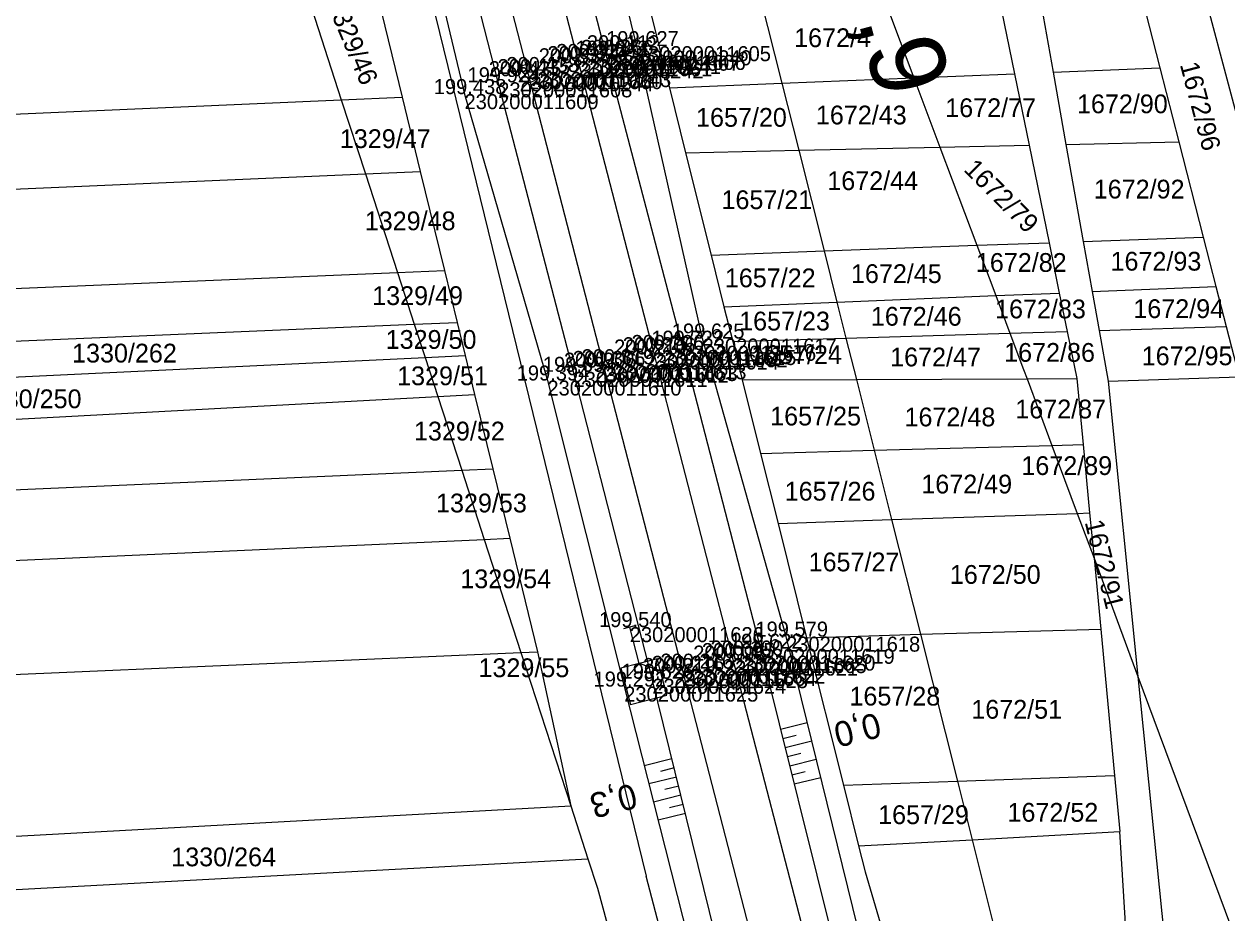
# Model space of a CAD drawing. Extents: x -563148 to -561712, y -1182311 to -1179502.
# Drawn here: x -562432.1 to -562336.1, y -1182118.9 to -1182047.9 of the extents above; entities that cross this region are included whole.
import ezdxf

# ---------------------------------------------------------------- set-up
doc = ezdxf.new("R2010")
doc.units = 0
for name, color, linetype in [('Vrstva 1', 7, 'Continuous'), ('Vrstva 4', 7, 'Continuous'), ('Vrstva 48', 7, 'Continuous'), ('Vrstva 49', 7, 'Continuous'), ('Vrstva 53', 7, 'Continuous'), ('Vrstva 55', 7, 'Continuous'), ('Vrstva 57', 7, 'Continuous'), ('Vrstva 60', 7, 'Continuous'), ('Vrstva 61', 7, 'Continuous'), ('Vrstva 7', 7, 'Continuous')]:
    doc.layers.add(name, color=color, linetype=linetype)

msp = doc.modelspace()

# ---------------------------------------------------------------- linework, layer by layer
at = {"layer": 'Vrstva 1'}
for points in [[(-562431.456, -1181882.158), (-562425.093, -1181906.771), (-562419.091, -1181930.016), (-562412.913, -1181953.965), (-562405.427, -1181982.918), (-562399.924, -1182004.215), (-562394.072, -1182026.888), (-562387.874, -1182050.84), (-562381.86, -1182074.092), (-562375.538, -1182098.521), (-562369.352, -1182122.433), (-562362.844, -1182147.635), (-562356.836, -1182170.919), (-562350.524, -1182195.336)], [(-562435.353, -1181883.455), (-562429.043, -1181907.884), (-562423.025, -1181931.202), (-562416.86, -1181955.033), (-562409.363, -1181984.042), (-562403.855, -1182005.364), (-562398.009, -1182028.011), (-562391.856, -1182051.875), (-562385.852, -1182075.188), (-562379.546, -1182099.541), (-562373.358, -1182123.485), (-562366.843, -1182148.681), (-562360.825, -1182171.976), (-562354.524, -1182196.409)]]:
    msp.add_lwpolyline(points, dxfattribs=at)
at = {"layer": 'Vrstva 4'}
for points in [[(-562356.597, -1182197.058), (-562363.671, -1182172.63), (-562369.111, -1182150.394), (-562376.003, -1182124.384), (-562381.959, -1182100.171), (-562388.242, -1182075.655), (-562394.258, -1182052.529), (-562401.091, -1182025.773), (-562406.12, -1182006.052), (-562411.703, -1181984.696), (-562419.188, -1181956.156), (-562425.491, -1181931.882), (-562431.354, -1181908.293), (-562438.222, -1181883.645), (-562444.124, -1181860.119), (-562450.397, -1181835.425), (-562455.984, -1181813.76), (-562461.844, -1181791.501), (-562470.013, -1181759.746), (-562475.447, -1181735.97), (-562481.267, -1181709.546), (-562485.292, -1181688.623), (-562489.631, -1181662.779), (-562492.854, -1181639.283)], [(-562429.083, -1181881.427), (-562423.039, -1181906.026), (-562416.991, -1181929.289), (-562410.946, -1181952.751), (-562403.313, -1181982.397), (-562397.583, -1182003.414), (-562392.555, -1182023.727), (-562385.634, -1182050.403), (-562379.578, -1182073.569), (-562373.303, -1182097.775), (-562367.317, -1182121.855), (-562360.795, -1182147.202), (-562354.718, -1182170.426), (-562348.388, -1182194.775)]]:
    msp.add_lwpolyline(points, dxfattribs=at)
at = {"layer": 'Vrstva 48'}
for p, q in [((-562371.705, -1182104.204), (-562369.577, -1182103.675)), ((-562371.524, -1182104.932), (-562370.461, -1182104.668)), ((-562371.343, -1182105.66), (-562369.219, -1182105.132)), ((-562380.385, -1182106.569), (-562382.596, -1182107.113)), ((-562371.162, -1182106.388), (-562370.101, -1182106.124)), ((-562370.981, -1182107.116), (-562368.86, -1182106.588)), ((-562380.206, -1182107.297), (-562381.309, -1182107.569)), ((-562370.8, -1182107.844), (-562369.74, -1182107.58)), ((-562380.027, -1182108.026), (-562382.227, -1182108.567)), ((-562370.619, -1182108.571), (-562368.502, -1182108.045)), ((-562379.669, -1182109.482), (-562381.858, -1182110.021)), ((-562379.848, -1182108.754), (-562380.945, -1182109.024)), ((-562379.489, -1182110.211), (-562380.581, -1182110.479)), ((-562379.31, -1182110.939), (-562381.489, -1182111.475))]:
    msp.add_line(p, q, dxfattribs=at)
at = {"layer": 'Vrstva 49'}
for points in [[(-562356.597, -1182197.058), (-562363.671, -1182172.63), (-562369.111, -1182150.394), (-562376.003, -1182124.384), (-562381.959, -1182100.171), (-562388.242, -1182075.655), (-562394.258, -1182052.529), (-562401.091, -1182025.773), (-562406.12, -1182006.052), (-562411.703, -1181984.696), (-562419.188, -1181956.156), (-562425.491, -1181931.882), (-562431.354, -1181908.293), (-562438.222, -1181883.645), (-562444.124, -1181860.119), (-562450.397, -1181835.425), (-562455.984, -1181813.76), (-562461.844, -1181791.501), (-562470.013, -1181759.746), (-562475.447, -1181735.97), (-562481.267, -1181709.546), (-562485.292, -1181688.623), (-562489.631, -1181662.779), (-562492.854, -1181639.283)], [(-562348.388, -1182194.775), (-562346.233, -1182193.909), (-562352.64, -1182170.226), (-562359.021, -1182146.828), (-562365.116, -1182121.8), (-562371.268, -1182096.806), (-562377.938, -1182072.997), (-562383.189, -1182049.641), (-562389.659, -1182023.356), (-562394.989, -1182002.824), (-562400.393, -1181981.55), (-562407.655, -1181951.839), (-562413.753, -1181928.351), (-562419.93, -1181905.004), (-562426.042, -1181880.285)], [(-562429.083, -1181881.427), (-562423.039, -1181906.026), (-562416.991, -1181929.289), (-562410.946, -1181952.751), (-562403.313, -1181982.397), (-562397.583, -1182003.414), (-562392.555, -1182023.727), (-562385.634, -1182050.403), (-562379.578, -1182073.569), (-562373.303, -1182097.775), (-562367.317, -1182121.855), (-562360.795, -1182147.202), (-562354.718, -1182170.426), (-562348.388, -1182194.775)], [(-562439.741, -1181884.96), (-562433.646, -1181909.277), (-562427.61, -1181932.656), (-562421.237, -1181957.617), (-562414.263, -1181985.119), (-562408.778, -1182006.666), (-562403.486, -1182026.149), (-562396.951, -1182053.474), (-562390.332, -1182076.348), (-562384.199, -1182100.797), (-562378.1, -1182124.825), (-562372.04, -1182148.774), (-562365.699, -1182172.919), (-562358.847, -1182197.091), (-562356.597, -1182197.058)]]:
    msp.add_lwpolyline(points, dxfattribs=at)
at = {"layer": 'Vrstva 53'}
for p, q in [((-562383.3, -1182042.07), (-562380.58, -1182052.97)), ((-562399.59, -1182045.91), (-562382.44, -1182115.94)), ((-562380.58, -1182052.97), (-562379.29, -1182058.16)), ((-562379.29, -1182058.16), (-562377.25, -1182066.33)), ((-562377.25, -1182066.33), (-562376.23, -1182070.45)), ((-562376.23, -1182070.45), (-562375.53, -1182073.24)), ((-562375.53, -1182073.24), (-562374.77, -1182076.29)), ((-562374.77, -1182076.29), (-562373.3, -1182082.17)), ((-562373.3, -1182082.17), (-562371.91, -1182087.77)), ((-562371.91, -1182087.77), (-562369.63, -1182096.89)), ((-562369.63, -1182096.89), (-562366.69, -1182108.67)), ((-562366.69, -1182108.67), (-562365.48, -1182113.52)), ((-562356.42, -1182113.03), (-562344.61, -1182112.38)), ((-562341.98, -1182156.11), (-562344.61, -1182112.38)), ((-562365.48, -1182113.52), (-562356.42, -1182113.03)), ((-562356.42, -1182113.03), (-562344.71, -1182159.58)), ((-562365.48, -1182113.52), (-562364.96, -1182115.6)), ((-562364.45, -1182184.72), (-562382.44, -1182115.94)), ((-562364.96, -1182115.6), (-562344.91, -1182183.41))]:
    msp.add_line(p, q, dxfattribs=at)
at = {"layer": 'Vrstva 55'}
for p, q in [((-562374.32, -1182041.85), (-562371.61, -1182052.6)), ((-562355.18, -1182041.39), (-562353.04, -1182051.84)), ((-562351.78, -1182041.39), (-562349.95, -1182051.71)), ((-562410.36, -1182042.92), (-562406.79, -1182053.92)), ((-562404.05, -1182045.04), (-562401.94, -1182053.71)), ((-562343.19, -1182044.49), (-562341.43, -1182051.36)), ((-562338.04, -1182044.82), (-562329.82, -1182075.89)), ((-562363.26, -1182046.36), (-562361.07, -1182052.17)), ((-562361.07, -1182052.17), (-562353.04, -1182051.84)), ((-562353.04, -1182051.84), (-562351.87, -1182057.55)), ((-562349.95, -1182051.71), (-562341.43, -1182051.36)), ((-562349.95, -1182051.71), (-562348.92, -1182057.49)), ((-562341.43, -1182051.36), (-562339.9, -1182057.29)), ((-562380.58, -1182052.97), (-562371.61, -1182052.6)), ((-562371.61, -1182052.6), (-562361.07, -1182052.17)), ((-562371.61, -1182052.6), (-562370.26, -1182057.96)), ((-562361.07, -1182052.17), (-562358.99, -1182057.71)), ((-562406.79, -1182053.92), (-562401.94, -1182053.71)), ((-562401.94, -1182053.71), (-562400.48, -1182059.66)), ((-562615.94, -1182063.02), (-562406.79, -1182053.92)), ((-562406.79, -1182053.92), (-562404.86, -1182059.85)), ((-562358.99, -1182057.71), (-562351.87, -1182057.55)), ((-562351.87, -1182057.55), (-562350.27, -1182065.34)), ((-562348.92, -1182057.49), (-562339.9, -1182057.29)), ((-562348.92, -1182057.49), (-562347.54, -1182065.24)), ((-562339.9, -1182057.29), (-562337.95, -1182064.89)), ((-562379.29, -1182058.16), (-562370.26, -1182057.96)), ((-562370.26, -1182057.96), (-562358.99, -1182057.71)), ((-562370.26, -1182057.96), (-562368.24, -1182066)), ((-562358.99, -1182057.71), (-562356.03, -1182065.55)), ((-562621.03, -1182069.13), (-562404.86, -1182059.85)), ((-562404.86, -1182059.85), (-562400.48, -1182059.66)), ((-562404.86, -1182059.85), (-562402.31, -1182067.71)), ((-562400.48, -1182059.66), (-562398.56, -1182067.55)), ((-562356.03, -1182065.55), (-562350.27, -1182065.34)), ((-562350.27, -1182065.34), (-562349.45, -1182069.36)), ((-562347.54, -1182065.24), (-562337.95, -1182064.89)), ((-562347.54, -1182065.24), (-562346.83, -1182069.25)), ((-562337.95, -1182064.89), (-562336.94, -1182068.85)), ((-562377.25, -1182066.33), (-562368.24, -1182066)), ((-562368.24, -1182066), (-562356.03, -1182065.55)), ((-562368.24, -1182066), (-562367.21, -1182070.08)), ((-562356.03, -1182065.55), (-562354.52, -1182069.56)), ((-562599.04, -1182076), (-562402.31, -1182067.71)), ((-562402.31, -1182067.71), (-562398.56, -1182067.55)), ((-562402.31, -1182067.71), (-562400.96, -1182071.85)), ((-562398.56, -1182067.55), (-562397.54, -1182071.71)), ((-562346.83, -1182069.25), (-562336.94, -1182068.85)), ((-562336.94, -1182068.85), (-562336.12, -1182072.04)), ((-562376.23, -1182070.45), (-562367.21, -1182070.08)), ((-562367.21, -1182070.08), (-562354.52, -1182069.56)), ((-562367.21, -1182070.08), (-562366.49, -1182072.96)), ((-562354.52, -1182069.56), (-562349.45, -1182069.36)), ((-562354.52, -1182069.56), (-562353.39, -1182072.56)), ((-562349.45, -1182069.36), (-562348.82, -1182072.43)), ((-562346.83, -1182069.25), (-562346.28, -1182072.35)), ((-562459.51, -1182074.32), (-562400.96, -1182071.85)), ((-562400.96, -1182071.85), (-562397.54, -1182071.71)), ((-562400.96, -1182071.85), (-562400.1, -1182074.5)), ((-562397.54, -1182071.71), (-562396.9, -1182074.34)), ((-562346.28, -1182072.35), (-562336.12, -1182072.04)), ((-562336.12, -1182072.04), (-562335.09, -1182076.06)), ((-562375.53, -1182073.24), (-562366.49, -1182072.96)), ((-562366.49, -1182072.96), (-562353.39, -1182072.56)), ((-562366.49, -1182072.96), (-562365.66, -1182076.26)), ((-562353.39, -1182072.56), (-562348.82, -1182072.43)), ((-562353.39, -1182072.56), (-562352.3, -1182075.47)), ((-562348.82, -1182072.43), (-562348.05, -1182076.2)), ((-562346.28, -1182072.35), (-562345.56, -1182076.39)), ((-562459.6, -1182077.36), (-562400.1, -1182074.5)), ((-562400.1, -1182074.5), (-562396.9, -1182074.34)), ((-562400.1, -1182074.5), (-562399.09, -1182077.62)), ((-562396.9, -1182074.34), (-562396.14, -1182077.46)), ((-562352.3, -1182075.47), (-562352.02, -1182076.21)), ((-562374.77, -1182076.29), (-562365.66, -1182076.26)), ((-562365.66, -1182076.26), (-562352.02, -1182076.21)), ((-562365.66, -1182076.26), (-562364.24, -1182081.92)), ((-562352.02, -1182076.21), (-562348.05, -1182076.2)), ((-562352.02, -1182076.21), (-562350.04, -1182081.53)), ((-562348.05, -1182076.2), (-562347.55, -1182081.46)), ((-562345.56, -1182076.39), (-562335.09, -1182076.06)), ((-562345.56, -1182076.39), (-562343.17, -1182099.99)), ((-562459.47, -1182080.88), (-562399.09, -1182077.62)), ((-562399.09, -1182077.62), (-562396.14, -1182077.46)), ((-562399.09, -1182077.62), (-562397.17, -1182083.52)), ((-562396.14, -1182077.46), (-562394.69, -1182083.41)), ((-562364.24, -1182081.92), (-562350.04, -1182081.53)), ((-562350.04, -1182081.53), (-562347.55, -1182081.46)), ((-562350.04, -1182081.53), (-562348.02, -1182086.96)), ((-562347.55, -1182081.46), (-562347.03, -1182086.93)), ((-562373.3, -1182082.17), (-562364.24, -1182081.92)), ((-562364.24, -1182081.92), (-562362.84, -1182087.46)), ((-562585.71, -1182091.7), (-562397.17, -1182083.52)), ((-562397.17, -1182083.52), (-562394.69, -1182083.41)), ((-562397.17, -1182083.52), (-562395.38, -1182089.04)), ((-562394.69, -1182083.41), (-562393.34, -1182088.95)), ((-562362.84, -1182087.46), (-562348.02, -1182086.96)), ((-562348.02, -1182086.96), (-562347.03, -1182086.93)), ((-562348.02, -1182086.96), (-562346.68, -1182090.55)), ((-562347.03, -1182086.93), (-562346.68, -1182090.55)), ((-562371.91, -1182087.77), (-562362.84, -1182087.46)), ((-562362.84, -1182087.46), (-562360.54, -1182096.62)), ((-562585.31, -1182097.56), (-562395.38, -1182089.04)), ((-562395.38, -1182089.04), (-562393.34, -1182088.95)), ((-562395.38, -1182089.04), (-562392.45, -1182098.07)), ((-562393.34, -1182088.95), (-562391.12, -1182098.01)), ((-562346.68, -1182090.55), (-562346.14, -1182096.2)), ((-562346.68, -1182090.55), (-562343.17, -1182099.99)), ((-562369.63, -1182096.89), (-562360.54, -1182096.62)), ((-562360.54, -1182096.62), (-562346.14, -1182096.2)), ((-562360.54, -1182096.62), (-562357.59, -1182108.34)), ((-562346.14, -1182096.2), (-562345.04, -1182107.9)), ((-562392.45, -1182098.07), (-562391.12, -1182098.01)), ((-562391.12, -1182098.01), (-562388.47, -1182110.31)), ((-562625.93, -1182108.14), (-562392.45, -1182098.07)), ((-562392.45, -1182098.07), (-562388.47, -1182110.31)), ((-562343.17, -1182099.99), (-562333.43, -1182126.19)), ((-562343.17, -1182099.99), (-562338.01, -1182151.05)), ((-562366.69, -1182108.67), (-562357.59, -1182108.34)), ((-562357.59, -1182108.34), (-562345.04, -1182107.9)), ((-562357.59, -1182108.34), (-562356.42, -1182113.03)), ((-562345.04, -1182107.9), (-562344.61, -1182112.38)), ((-562462.21, -1182114.37), (-562388.47, -1182110.31)), ((-562388.47, -1182110.31), (-562387.09, -1182114.56)), ((-562461.82, -1182118.54), (-562387.09, -1182114.56)), ((-562387.09, -1182114.56), (-562386.33, -1182116.89)), ((-562386.33, -1182116.89), (-562385.09, -1182121.5))]:
    msp.add_line(p, q, dxfattribs=at)
at = {"layer": 'Vrstva 60'}
for p, q in [((-562384.733, -1182049.972), (-562384.733, -1182049.972)), ((-562383.189, -1182049.641), (-562383.189, -1182049.641)), ((-562387.874, -1182050.84), (-562387.874, -1182050.84)), ((-562387.178, -1182050.668), (-562387.178, -1182050.668)), ((-562385.634, -1182050.403), (-562385.634, -1182050.403)), ((-562385.199, -1182050.342), (-562385.199, -1182050.342)), ((-562391.856, -1182051.875), (-562391.856, -1182051.875)), ((-562391.155, -1182051.71), (-562391.155, -1182051.71)), ((-562388.569, -1182051.012), (-562388.569, -1182051.012)), ((-562394.258, -1182052.529), (-562394.258, -1182052.529)), ((-562392.557, -1182052.04), (-562392.557, -1182052.04)), ((-562396.951, -1182053.474), (-562396.951, -1182053.474)), ((-562377.938, -1182072.997), (-562377.938, -1182072.997)), ((-562381.164, -1182073.912), (-562381.164, -1182073.912)), ((-562379.578, -1182073.569), (-562379.578, -1182073.569)), ((-562382.556, -1182074.273), (-562382.556, -1182074.273)), ((-562381.86, -1182074.092), (-562381.86, -1182074.092)), ((-562388.242, -1182075.655), (-562388.242, -1182075.655)), ((-562386.558, -1182075.324), (-562386.558, -1182075.324)), ((-562385.852, -1182075.188), (-562385.852, -1182075.188)), ((-562385.145, -1182075.051), (-562385.145, -1182075.051)), ((-562390.332, -1182076.348), (-562390.332, -1182076.348)), ((-562383.757, -1182096.047), (-562383.757, -1182096.047)), ((-562371.268, -1182096.806), (-562371.268, -1182096.806)), ((-562373.303, -1182097.775), (-562373.303, -1182097.775)), ((-562376.227, -1182098.72), (-562376.227, -1182098.72)), ((-562375.538, -1182098.521), (-562375.538, -1182098.521)), ((-562374.849, -1182098.321), (-562374.849, -1182098.321)), ((-562380.239, -1182099.716), (-562380.239, -1182099.716)), ((-562379.546, -1182099.541), (-562379.546, -1182099.541)), ((-562378.853, -1182099.367), (-562378.853, -1182099.367)), ((-562384.199, -1182100.797), (-562384.199, -1182100.797)), ((-562381.959, -1182100.171), (-562381.959, -1182100.171))]:
    msp.add_line(p, q, dxfattribs=at)
at = {"layer": 'Vrstva 7'}
for p, q in [((-562385.199, -1182049.842), (-562385.199, -1182050.842)), ((-562384.745, -1182049.924), (-562384.721, -1182050.02)), ((-562385.699, -1182050.342), (-562384.699, -1182050.342)), ((-562383.273, -1182095.922), (-562384.241, -1182096.172)), ((-562383.005, -1182098.951), (-562383.757, -1182096.047))]:
    msp.add_line(p, q, dxfattribs=at)
for points in [[(-562383.005, -1182098.951), (-562384.457, -1182099.327), (-562383.705, -1182102.231), (-562380.801, -1182101.479), (-562381.553, -1182098.575), (-562383.005, -1182098.951)], [(-562381.302, -1182099.545), (-562383.005, -1182098.951), (-562384.206, -1182100.297)]]:
    msp.add_lwpolyline(points, dxfattribs=at)
for centre, radius in [((-562384.733, -1182049.972), 0.5), ((-562391.873, -1182051.811), 0.75)]:
    msp.add_circle(centre, radius, dxfattribs=at)

# ---------------------------------------------------------------- texts
at = {"layer": 'Vrstva 48'}
for s, rotation, p in [('0,0', 193.96008, (-562364.004, -1182102.846)), ('0,3', 194.24253, (-562383.488, -1182108.502))]:
    msp.add_text(s, height=2, rotation=rotation, dxfattribs=at).set_placement(p)
at = {"layer": 'Vrstva 57'}
for s, rotation, p in [('1329/46', 292.7565, (-562407.99, -1182046.2)), ('1672/96', 284.82354, (-562339.83, -1182051.11)), ('1672/79', 315, (-562357.16, -1182059.56)), ('1672/91', 283.76082, (-562347.43, -1182087.66))]:
    msp.add_text(s, height=1.5, rotation=rotation, dxfattribs=at).set_placement(p)
for s, p in [('1672/4', (-562370.63, -1182049.72)), ('1672/77', (-562358.56, -1182055.31)), ('1672/90', (-562348.04, -1182055)), ('1657/20', (-562378.46, -1182056.08)), ('1672/43', (-562368.89, -1182055.89)), ('1329/47', (-562406.906, -1182057.78)), ('1672/44', (-562367.98, -1182061.14)), ('1672/92', (-562346.7, -1182061.81)), ('1657/21', (-562376.43, -1182062.66)), ('1329/48', (-562404.915, -1182064.346)), ('1672/82', (-562356.114, -1182067.67)), ('1672/93', (-562345.36, -1182067.57)), ('1672/45', (-562366.09, -1182068.56)), ('1657/22', (-562376.16, -1182068.9)), ('1329/49', (-562404.323, -1182070.32)), ('1672/83', (-562354.58, -1182071.383)), ('1672/94', (-562343.54, -1182071.36)), ('1657/23', (-562375.02, -1182072.35)), ('1672/46', (-562364.5, -1182071.97)), ('1329/50', (-562403.246, -1182073.819)), ('1330/262', (-562428.29, -1182074.91)), ('1657/24', (-562374.06, -1182075.03)), ('1672/47', (-562362.96, -1182075.22)), ('1672/86', (-562353.854, -1182074.855)), ('1672/95', (-562342.87, -1182075.13)), ('1329/51', (-562402.332, -1182076.725)), ('1330/250', (-562435.9, -1182078.56)), ('1672/87', (-562352.966, -1182079.375)), ('1657/25', (-562372.54, -1182079.94)), ('1672/48', (-562361.81, -1182080.01)), ('1329/52', (-562400.986, -1182081.138)), ('1672/89', (-562352.481, -1182083.896)), ('1657/26', (-562371.38, -1182085.94)), ('1672/49', (-562360.47, -1182085.37)), ('1329/53', (-562399.223, -1182086.883)), ('1657/27', (-562369.47, -1182091.59)), ('1672/50', (-562358.19, -1182092.59)), ('1329/54', (-562397.286, -1182092.938)), ('1329/55', (-562395.833, -1182100.042)), ('1657/28', (-562366.21, -1182102.31)), ('1672/51', (-562356.48, -1182103.36)), ('1657/29', (-562363.92, -1182111.78)), ('1672/52', (-562353.59, -1182111.59)), ('1330/264', (-562420.37, -1182115.15))]:
    msp.add_text(s, height=1.5, dxfattribs=at).set_placement(p)
at = {"layer": 'Vrstva 60'}
for s, p in [('230200010240', (-562384.733, -1182051.172)), ('230200011605', (-562383.189, -1182050.841)), ('230200011661', (-562387.874, -1182052.04)), ('230200010241', (-562387.178, -1182051.868)), ('230200011607', (-562385.634, -1182051.603)), ('230200011606', (-562385.199, -1182051.542)), ('230200011660', (-562391.856, -1182053.075)), ('230200010243', (-562391.155, -1182052.91)), ('230200010242', (-562388.569, -1182052.212)), ('230200011608', (-562394.258, -1182053.729)), ('230200010244', (-562392.557, -1182053.24)), ('230200011609', (-562396.951, -1182054.674)), ('230200011617', (-562377.938, -1182074.197)), ('230200011615', (-562381.164, -1182075.112)), ('230200011616', (-562379.578, -1182074.769)), ('230200011614', (-562382.556, -1182075.473)), ('230200011662', (-562381.86, -1182075.292)), ('230200011611', (-562388.242, -1182076.855)), ('230200011612', (-562386.558, -1182076.524)), ('230200011663', (-562385.852, -1182076.388)), ('230200011613', (-562385.145, -1182076.251)), ('230200011610', (-562390.332, -1182077.548)), ('230200011626', (-562383.757, -1182097.247)), ('230200011618', (-562371.268, -1182098.006)), ('230200011619', (-562373.303, -1182098.975)), ('230200011621', (-562376.227, -1182099.92)), ('230200011665', (-562375.538, -1182099.721)), ('230200011620', (-562374.849, -1182099.521)), ('230200011623', (-562380.239, -1182100.916)), ('230200011664', (-562379.546, -1182100.741)), ('230200011622', (-562378.853, -1182100.567)), ('230200011625', (-562384.199, -1182101.997)), ('230200011624', (-562381.959, -1182101.371))]:
    msp.add_text(s, height=1.2, dxfattribs=at).set_placement(p)
at = {"layer": 'Vrstva 61'}
for s, p in [('200.112', (-562387.181, -1182049.972)), ('199.627', (-562385.641, -1182049.641)), ('200.335', (-562391.025, -1182051.012)), ('200.324', (-562390.325, -1182050.84)), ('200.324', (-562389.629, -1182050.668)), ('199.842', (-562388.082, -1182050.403)), ('200.366', (-562387.651, -1182050.342)), ('200.435', (-562395.013, -1182052.04)), ('200.435', (-562394.312, -1182051.875)), ('200.438', (-562393.609, -1182051.71)), ('199.924', (-562396.709, -1182052.529)), ('199.438', (-562399.405, -1182053.474)), ('199.625', (-562380.394, -1182072.997)), ('200.206', (-562384.312, -1182074.092)), ('200.206', (-562383.616, -1182073.912)), ('199.722', (-562382.026, -1182073.569)), ('200.306', (-562388.304, -1182075.188)), ('200.319', (-562387.599, -1182075.051)), ('200.210', (-562385.007, -1182074.273)), ('199.694', (-562390.693, -1182075.655)), ('200.306', (-562389.01, -1182075.324)), ('199.394', (-562392.783, -1182076.348)), ('199.540', (-562386.208, -1182096.047)), ('199.579', (-562373.722, -1182096.806)), ('199.622', (-562375.751, -1182097.775)), ('200.095', (-562378.683, -1182098.72)), ('200.095', (-562377.994, -1182098.521)), ('200.100', (-562377.3, -1182098.321)), ('199.626', (-562384.411, -1182100.171)), ('200.219', (-562382.693, -1182099.716)), ('200.216', (-562381.998, -1182099.541)), ('200.216', (-562381.305, -1182099.367)), ('199.292', (-562386.647, -1182100.797))]:
    msp.add_text(s, height=1.2, dxfattribs=at).set_placement(p)
at = {"layer": 'Vrstva 7'}
msp.add_text('59,9', height=6, rotation=284.45802, dxfattribs=at).set_placement((-562367.774, -1182038.92))

doc.saveas('drawing.dxf')
